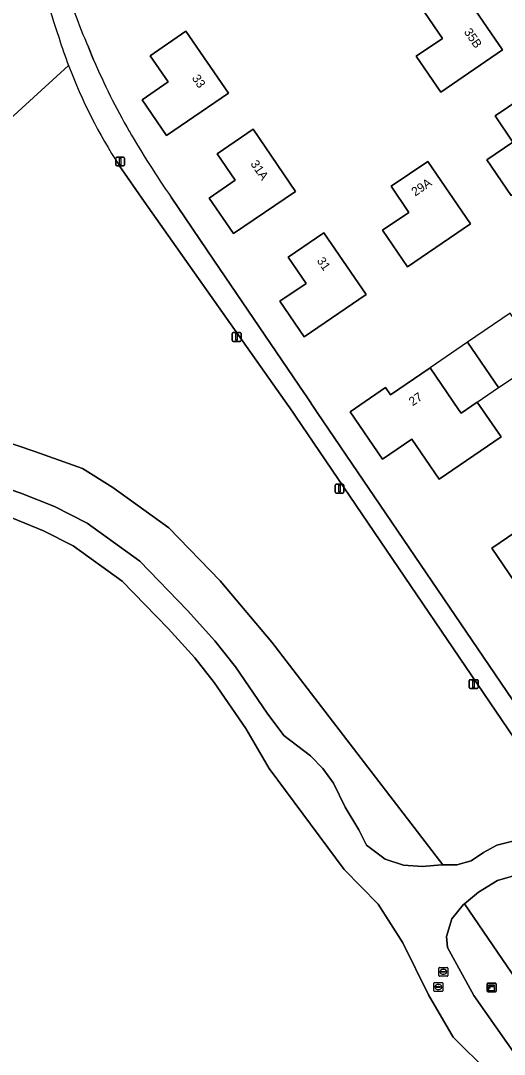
# Model space of a CAD drawing. Extents: x 155275 to 156265, y 382654 to 383635.
# Drawn here: x 155411.8 to 155466.8, y 383140.8 to 383258.3 of the extents above; entities that cross this region are included whole.
import ezdxf

# ---------------------------------------------------------------- set-up
doc = ezdxf.new("R2010")
doc.units = 0
for name, color, linetype in [('IMGEO_Erf', 7, 'Continuous'), ('IMGEO_Groenvoorziening', 7, 'Continuous'), ('IMGEO_Kast', 7, 'Continuous'), ('IMGEO_Lichtmast', 7, 'Continuous'), ('IMGEO_Pand', 7, 'Continuous'), ('IMGEO_Pand_nummerreeks', 7, 'Continuous'), ('IMGEO_Pand_overbouw', 7, 'Continuous'), ('IMGEO_Rioolput', 7, 'Continuous'), ('IMGEO_Voetpad_halfverhard', 7, 'Continuous'), ('IMGEO_Voetpad_open', 7, 'Continuous')]:
    doc.layers.add(name, color=color, linetype=linetype)

msp = doc.modelspace()

# ---------------------------------------------------------------- linework, layer by layer
at = {"layer": 'IMGEO_Erf'}
for points in [[(155428.92, 383238.24), (155433.77, 383231.09), (155444.08, 383215.94), (155444.19, 383215.77), (155445.52, 383213.79), (155474.85, 383170.58), (155512.73, 383196.49), (155448.88, 383290.13), (155420.3, 383270.55)], [(155419.52, 383255.3), (155420.11, 383253.88)], [(155468.55, 383193.62), (155465.34, 383198.36), (155476.24, 383205.79)]]:
    msp.add_lwpolyline(points, dxfattribs=at)
for points in [[(155456.77, 383254.27), (155459.75, 383256.3), (155457.7, 383259.29), (155461.75, 383262.05), (155466.57, 383255.01), (155459.55, 383250.19)], [(155428.39, 383245.27), (155425.62, 383249.31), (155428.6, 383251.38), (155426.56, 383254.33), (155430.61, 383257.14), (155435.43, 383250.08)], [(155465.72, 383247.49), (155469.81, 383250.28), (155474.6, 383243.27), (155467.56, 383238.46), (155464.78, 383242.51), (155467.74, 383244.52)], [(155436.02, 383234.12), (155433.24, 383238.16), (155436.2, 383240.2), (155434.16, 383243.2), (155438.24, 383245.97), (155443.05, 383238.92)], [(155452.95, 383234.51), (155455.92, 383236.53), (155453.92, 383239.49), (155458.08, 383242.32), (155462.91, 383235.22), (155455.79, 383230.35)], [(155444.04, 383222.38), (155441.27, 383226.44), (155444.25, 383228.45), (155442.22, 383231.43), (155446.28, 383234.21), (155451.08, 383227.18)], [(155453.28, 383216.6), (155453.84, 383215.78), (155458.35, 383218.86), (155461.58, 383214.13), (155461.87, 383213.71), (155463.7, 383214.96), (155466.4, 383211.02), (155459.35, 383206.19), (155456.25, 383210.73), (155452.94, 383208.47), (155449.27, 383213.87)]]:
    msp.add_lwpolyline(points, close=True, dxfattribs=at)
for centre, radius, start, end in [((155494.03, 383287.49), 81.16, 197.3689, 203.3673), ((155487.89, 383282.61), 73.61, 202.9709, 210.0234), ((155528.81, 383306.73), 121.11, 210.2146, 214.4373)]:
    msp.add_arc(centre, radius, start, end, dxfattribs=at)
at = {"layer": 'IMGEO_Groenvoorziening'}
for points in [[(155381.63, 383229.41), (155385.36, 383224.06), (155417.27, 383253.23)], [(155417.27, 383253.23), (155385.36, 383224.06), (155387.41, 383221.12)], [(155442.32, 383214.41), (155442.28, 383214.46), (155425.86, 383237.78), (155423.01, 383241.86)], [(155372.2, 383202.28), (155372.51, 383201.68), (155388.96, 383210.31), (155393.94, 383212.01), (155397.68, 383212.16), (155401.05, 383212.16), (155406.49, 383211.64), (155409.53, 383210.66), (155413.45, 383209.36), (155418.85, 383207.42), (155422.29, 383205.23), (155428.68, 383200.68), (155434.48, 383194.63), (155440.37, 383187.68), (155459.78, 383162.34), (155461.36, 383162.34), (155463.01, 383162.79), (155464.41, 383163.77), (155465.92, 383164.58), (155468.34, 383165.21), (155474.68, 383166.56), (155474.79, 383166.6), (155442.32, 383214.41)], [(155407.94, 383205.92), (155411.86, 383204.61), (155415.69, 383203.07), (155419.37, 383201.18), (155425.35, 383196.87), (155430.78, 383191.26), (155433.9, 383187.83), (155436.24, 383184.86), (155439.83, 383179.6), (155441.74, 383177.07), (155444.76, 383174.76), (155446.17, 383173.3), (155447.36, 383171.65), (155448.69, 383168.92), (155450.26, 383166.32), (155451.1, 383164.6), (155453.23, 383163.01), (155455.3, 383162.33), (155457.48, 383162.15), (155459.65, 383162.34), (155459.78, 383162.34), (155440.37, 383187.68), (155434.48, 383194.63), (155428.68, 383200.68), (155422.29, 383205.23), (155418.85, 383207.42), (155413.45, 383209.36), (155409.53, 383210.66)], [(155464.94, 383138.83), (155460.95, 383142.74), (155458.15, 383147.57), (155455.23, 383153.48), (155452.44, 383157.87), (155448.58, 383161.82), (155440.05, 383173.3), (155437.4, 383177.85), (155433.82, 383183.08), (155431.61, 383185.89), (155428.59, 383189.21), (155423.37, 383194.6), (155417.81, 383198.6), (155414.44, 383200.34), (155410.83, 383201.8)], [(155462.23, 383157.91), (155462.08, 383157.79), (155460.8, 383156.2), (155460.21, 383154.22), (155460.31, 383152.94), (155463.29, 383147.49), (155476.06, 383129.31), (155480.08, 383123.25), (155485.32, 383114.54), (155492.39, 383101.86), (155501.64, 383091.21), (155505.49, 383085.67), (155519.41, 383065.24), (155519.67, 383065.42), (155525.58, 383056.8)], [(155531.84, 383055.02), (155532.26, 383055.3), (155462.23, 383157.91)]]:
    msp.add_lwpolyline(points, dxfattribs=at)
msp.add_lwpolyline([(155480.03, 383158.88), (155477.83, 383162.13), (155472.81, 383162.13), (155468.62, 383161.33), (155465.99, 383160.57), (155463.85, 383159.26), (155462.23, 383157.91), (155532.26, 383055.3), (155545.15, 383064.13), (155544.46, 383065.14), (155543.8, 383064.76), (155530.65, 383083.86), (155531.33, 383084.3), (155531.27, 383084.39), (155521.54, 383098.33)], close=True, dxfattribs=at)
for centre, radius, start, end in [((155635.7, 383329.55), 231.39, 194.7339, 198.4479), ((155471.85, 383273.8), 58.33, 197.432, 200.6455), ((155472.58, 383274.03), 59.09, 200.6064, 212.9901)]:
    msp.add_arc(centre, radius, start, end, dxfattribs=at)
at = {"layer": 'IMGEO_Kast'}
for p, q in [((155464.83, 383147.98), (155464.83, 383148.82)), ((155464.83, 383148.82), (155464.83, 383147.98)), ((155464.9, 383148.91), (155465.74, 383148.91)), ((155465.74, 383148.91), (155464.9, 383148.91)), ((155465.83, 383148.83), (155465.83, 383147.99)), ((155465.83, 383147.99), (155465.83, 383148.83)), ((155465.75, 383147.91), (155464.91, 383147.91)), ((155464.91, 383147.91), (155465.75, 383147.91))]:
    msp.add_line(p, q, dxfattribs=at)
for points in [[(155465.02, 383148.7), (155465.62, 383148.7), (155465.62, 383148.61), (155465.02, 383148.61), (155465.02, 383148.7)], [(155465.02, 383148.52), (155465.62, 383148.52), (155465.62, 383148.03), (155465.02, 383148.03), (155465.02, 383148.52)]]:
    msp.add_lwpolyline(points, dxfattribs=at)
msp.add_circle((155465.11, 383148.37), 0.0377, dxfattribs=at)
for centre, start, end in [((155464.91, 383148.83), 92.4484, 184.2845), ((155464.91, 383148.83), 92.4484, 184.2845), ((155465.75, 383148.83), 2.4484, 94.2845), ((155465.75, 383148.83), 2.4484, 94.2845), ((155464.91, 383147.99), 182.4484, 274.2845), ((155464.91, 383147.99), 182.4484, 274.2845), ((155465.75, 383147.99), 272.4484, 4.2845), ((155465.75, 383147.99), 272.4484, 4.2845)]:
    msp.add_arc(centre, 0.0779, start, end, dxfattribs=at)
at = {"layer": 'IMGEO_Lichtmast'}
for p, q in [((155422.64, 383241.91), (155422.64, 383242.71)), ((155422.64, 383242.71), (155422.64, 383241.91)), ((155422.74, 383242.81), (155423.53, 383242.81)), ((155423.53, 383242.81), (155422.74, 383242.81)), ((155423.63, 383242.71), (155423.63, 383241.91)), ((155423.63, 383241.91), (155423.63, 383242.71)), ((155423.53, 383241.81), (155422.74, 383241.81)), ((155422.74, 383241.81), (155423.53, 383241.81)), ((155435.87, 383221.96), (155435.87, 383222.76)), ((155435.87, 383222.76), (155435.87, 383221.96)), ((155435.97, 383222.86), (155436.76, 383222.86)), ((155436.76, 383222.86), (155435.97, 383222.86)), ((155436.86, 383222.76), (155436.86, 383221.96)), ((155436.86, 383221.96), (155436.86, 383222.76)), ((155436.76, 383221.86), (155435.97, 383221.86)), ((155435.97, 383221.86), (155436.76, 383221.86)), ((155447.55, 383204.72), (155447.55, 383205.52)), ((155447.55, 383205.52), (155447.55, 383204.72)), ((155447.65, 383205.62), (155448.44, 383205.62)), ((155448.44, 383205.62), (155447.65, 383205.62)), ((155448.44, 383204.62), (155447.65, 383204.62)), ((155447.65, 383204.62), (155448.44, 383204.62)), ((155448.54, 383205.52), (155448.54, 383204.72)), ((155448.54, 383204.72), (155448.54, 383205.52)), ((155462.79, 383182.5), (155462.79, 383183.3)), ((155462.79, 383183.3), (155462.79, 383182.5)), ((155462.89, 383183.4), (155463.68, 383183.4)), ((155463.68, 383183.4), (155462.89, 383183.4)), ((155463.68, 383182.4), (155462.89, 383182.4)), ((155462.89, 383182.4), (155463.68, 383182.4)), ((155463.78, 383183.3), (155463.78, 383182.5)), ((155463.78, 383182.5), (155463.78, 383183.3))]:
    msp.add_line(p, q, dxfattribs=at)
for points in [[(155423.06, 383242.69), (155423.21, 383242.69), (155423.21, 383241.94), (155423.06, 383241.94), (155423.06, 383242.69)], [(155436.29, 383222.74), (155436.44, 383222.74), (155436.44, 383221.99), (155436.29, 383221.99), (155436.29, 383222.74)], [(155447.97, 383205.5), (155448.12, 383205.5), (155448.12, 383204.75), (155447.97, 383204.75), (155447.97, 383205.5)], [(155463.21, 383183.27), (155463.36, 383183.27), (155463.36, 383182.52), (155463.21, 383182.52), (155463.21, 383183.27)]]:
    msp.add_lwpolyline(points, dxfattribs=at)
for centre, start, end in [((155422.74, 383242.71), 90, 180), ((155422.74, 383242.71), 90, 180), ((155423.53, 383242.71), 0, 90), ((155423.53, 383242.71), 360, 90), ((155422.74, 383241.91), 180, 270), ((155422.74, 383241.91), 180, 270), ((155423.53, 383241.91), 270, 0), ((155423.53, 383241.91), 270, 0), ((155435.97, 383222.76), 90, 180), ((155435.97, 383222.76), 90, 180), ((155436.76, 383222.76), 0, 90), ((155436.76, 383222.76), 360, 90), ((155435.97, 383221.96), 180, 270), ((155435.97, 383221.96), 180, 270), ((155436.76, 383221.96), 270, 0), ((155436.76, 383221.96), 270, 0), ((155447.65, 383205.52), 90, 180), ((155447.65, 383205.52), 90, 180), ((155447.65, 383204.72), 180, 270), ((155447.65, 383204.72), 180, 270), ((155448.44, 383205.52), 0, 90), ((155448.44, 383205.52), 360, 90), ((155448.44, 383204.72), 270, 0), ((155448.44, 383204.72), 270, 0), ((155462.89, 383183.3), 90, 180), ((155462.89, 383183.3), 90, 180), ((155462.89, 383182.5), 180, 270), ((155462.89, 383182.5), 180, 270), ((155463.68, 383183.3), 0, 90), ((155463.68, 383183.3), 360, 90), ((155463.68, 383182.5), 270, 0), ((155463.68, 383182.5), 270, 0)]:
    msp.add_arc(centre, 0.1, start, end, dxfattribs=at)
at = {"layer": 'IMGEO_Pand'}
for points in [[(155461.75, 383262.05), (155457.7, 383259.29), (155459.75, 383256.3), (155456.77, 383254.27), (155459.55, 383250.19), (155466.57, 383255.01)], [(155430.61, 383257.14), (155426.56, 383254.33), (155428.6, 383251.38), (155425.62, 383249.31), (155428.39, 383245.27), (155435.43, 383250.08)], [(155469.81, 383250.28), (155465.72, 383247.49), (155467.74, 383244.52), (155464.78, 383242.51), (155467.56, 383238.46), (155474.6, 383243.27)], [(155438.24, 383245.97), (155434.16, 383243.2), (155436.2, 383240.2), (155433.24, 383238.16), (155436.02, 383234.12), (155443.05, 383238.92)], [(155458.08, 383242.32), (155453.92, 383239.49), (155455.92, 383236.53), (155452.95, 383234.51), (155455.79, 383230.35), (155462.91, 383235.22)], [(155446.28, 383234.21), (155442.22, 383231.43), (155444.25, 383228.45), (155441.27, 383226.44), (155444.04, 383222.38), (155451.08, 383227.18)], [(155463.7, 383214.96), (155461.87, 383213.71), (155461.58, 383214.13), (155458.35, 383218.86), (155453.84, 383215.78), (155453.28, 383216.6), (155449.27, 383213.87), (155452.94, 383208.47), (155456.25, 383210.73), (155459.35, 383206.19), (155466.4, 383211.02)], [(155480.83, 383202.03), (155482.22, 383202.97), (155476.21, 383211.82), (155473.43, 383209.92), (155476.24, 383205.79), (155465.34, 383198.36), (155468.55, 383193.62), (155471.85, 383195.86)]]:
    msp.add_lwpolyline(points, close=True, dxfattribs=at)
at = {"layer": 'IMGEO_Pand_overbouw'}
for points in [[(155462.6, 383221.76), (155466.12, 383216.61), (155466.97, 383217.18), (155470.96, 383219.9), (155470.82, 383220.1), (155470.67, 383220.31), (155467.43, 383225.06)], [(155462.6, 383221.76), (155458.35, 383218.86), (155461.58, 383214.13), (155461.87, 383213.71), (155463.7, 383214.96), (155466.12, 383216.61)]]:
    msp.add_lwpolyline(points, close=True, dxfattribs=at)
at = {"layer": 'IMGEO_Rioolput'}
for p, q in [((155459.34, 383149.76), (155459.34, 383150.61)), ((155459.42, 383150.69), (155460.27, 383150.69)), ((155460.34, 383150.61), (155460.34, 383149.76)), ((155460.27, 383149.69), (155459.42, 383149.69)), ((155459.6, 383150.18), (155459.6, 383150.19)), ((155460.04, 383150.14), (155459.64, 383150.14)), ((155459.65, 383150.23), (155460.04, 383150.23)), ((155459.83, 383150.47), (155459.86, 383150.47)), ((155459.85, 383149.91), (155459.83, 383149.91)), ((155460.09, 383150.19), (155460.09, 383150.18)), ((155458.76, 383148.04), (155458.76, 383148.89)), ((155458.84, 383148.96), (155459.69, 383148.96)), ((155459.02, 383148.46), (155459.02, 383148.47)), ((155459.46, 383148.42), (155459.06, 383148.42)), ((155459.07, 383148.51), (155459.46, 383148.51)), ((155459.25, 383148.74), (155459.28, 383148.74)), ((155459.27, 383148.18), (155459.25, 383148.18)), ((155459.51, 383148.47), (155459.51, 383148.46)), ((155459.77, 383148.89), (155459.77, 383148.04)), ((155459.69, 383147.96), (155458.84, 383147.96))]:
    msp.add_line(p, q, dxfattribs=at)
for points in [[(155459.34, 383149.76), (155459.34, 383150.61)], [(155459.42, 383150.69), (155460.27, 383150.69)], [(155460.34, 383150.61), (155460.34, 383149.76)], [(155460.27, 383149.69), (155459.42, 383149.69)], [(155458.76, 383148.04), (155458.76, 383148.89)], [(155458.84, 383148.96), (155459.69, 383148.96)], [(155459.77, 383148.89), (155459.77, 383148.04)], [(155459.69, 383147.96), (155458.84, 383147.96)]]:
    msp.add_lwpolyline(points, dxfattribs=at)
for centre, radius, start, end in [((155459.42, 383150.61), 0.0765, 91.552, 178.448), ((155459.42, 383150.61), 0.0765, 91.552, 178.448), ((155460.27, 383150.61), 0.0765, 1.552, 88.448), ((155460.27, 383150.61), 0.0765, 1.552, 88.448), ((155459.42, 383149.76), 0.0765, 181.552, 268.448), ((155459.42, 383149.76), 0.0765, 181.552, 268.448), ((155459.64, 383150.19), 0.0403, 85.8775, 175.7526), ((155459.64, 383150.18), 0.0366, 178.938, 274.7102), ((155460.05, 383150.19), 0.0386, 1.7309, 96.639), ((155460.04, 383150.19), 0.043, 264.8664, 352.4533), ((155460.27, 383149.76), 0.0765, 271.552, 358.448), ((155460.27, 383149.76), 0.0765, 271.552, 358.448), ((155458.84, 383148.89), 0.0765, 91.552, 178.448), ((155458.84, 383148.89), 0.0765, 91.552, 178.448), ((155459.06, 383148.47), 0.0403, 85.8775, 175.7526), ((155459.06, 383148.46), 0.0366, 178.938, 274.7102), ((155459.47, 383148.47), 0.0386, 1.7309, 96.639), ((155459.46, 383148.46), 0.043, 264.8664, 352.4533), ((155459.69, 383148.89), 0.0765, 1.552, 88.448), ((155459.69, 383148.89), 0.0765, 1.552, 88.448), ((155458.84, 383148.04), 0.0765, 181.552, 268.448), ((155458.84, 383148.04), 0.0765, 181.552, 268.448), ((155459.69, 383148.04), 0.0765, 271.552, 358.448), ((155459.69, 383148.04), 0.0765, 271.552, 358.448)]:
    msp.add_arc(centre, radius, start, end, dxfattribs=at)
for centre, major_axis, ratio, start_param, end_param in [((155459.83, 383150.19), (-0.387, 0.002), 0.722429, 4.712389, 7.853982), ((155459.85, 383150.19), (-0.39, 0.002), 0.717154, 1.570796, 4.712389), ((155459.25, 383148.46), (-0.387, 0.002), 0.722429, 4.712389, 7.853982), ((155459.28, 383148.46), (-0.39, 0.002), 0.717154, 1.570796, 4.712389)]:
    msp.add_ellipse(centre, major_axis=major_axis, ratio=ratio, start_param=start_param, end_param=end_param, dxfattribs=at)
at = {"layer": 'IMGEO_Voetpad_halfverhard'}
for points in [[(155468.34, 383165.21), (155465.92, 383164.58), (155464.41, 383163.77), (155463.01, 383162.79), (155461.36, 383162.34), (155459.78, 383162.34), (155459.65, 383162.34), (155457.48, 383162.15), (155455.3, 383162.33), (155453.23, 383163.01), (155451.1, 383164.6), (155450.26, 383166.32), (155448.69, 383168.92), (155447.36, 383171.65), (155446.17, 383173.3), (155444.76, 383174.76), (155441.74, 383177.07), (155439.83, 383179.6), (155436.24, 383184.86), (155433.9, 383187.83), (155430.78, 383191.26), (155425.35, 383196.87), (155419.37, 383201.18), (155415.69, 383203.07), (155411.86, 383204.61), (155407.94, 383205.92)], [(155410.83, 383201.8), (155414.44, 383200.34), (155417.81, 383198.6), (155423.37, 383194.6), (155428.59, 383189.21), (155431.61, 383185.89), (155433.82, 383183.08), (155437.4, 383177.85), (155440.05, 383173.3), (155448.58, 383161.82), (155452.44, 383157.87), (155455.23, 383153.48), (155458.15, 383147.57), (155460.95, 383142.74), (155464.94, 383138.83)], [(155460.31, 383152.94), (155460.21, 383154.22), (155460.8, 383156.2), (155462.08, 383157.79), (155462.23, 383157.91), (155463.85, 383159.26), (155465.99, 383160.57), (155468.62, 383161.33)], [(155476.06, 383129.31), (155463.29, 383147.49), (155460.31, 383152.94)]]:
    msp.add_lwpolyline(points, dxfattribs=at)
at = {"layer": 'IMGEO_Voetpad_open'}
for points in [[(155420.11, 383253.88), (155419.52, 383255.3)], [(155423.01, 383241.86), (155425.86, 383237.78), (155442.28, 383214.46), (155442.32, 383214.41), (155474.79, 383166.6), (155476.98, 383167.45), (155474.85, 383170.58), (155445.52, 383213.79), (155444.19, 383215.77), (155444.08, 383215.94), (155433.77, 383231.09), (155428.92, 383238.24)]]:
    msp.add_lwpolyline(points, dxfattribs=at)
for centre, radius, start, end in [((155635.7, 383329.55), 231.39, 194.7339, 198.4479), ((155494.03, 383287.49), 81.16, 197.3689, 203.3673), ((155471.85, 383273.8), 58.33, 197.432, 200.6455), ((155472.58, 383274.03), 59.09, 200.6064, 212.9901), ((155487.89, 383282.61), 73.61, 202.9709, 210.0234), ((155528.81, 383306.73), 121.11, 210.2146, 214.4373)]:
    msp.add_arc(centre, radius, start, end, dxfattribs=at)

# ---------------------------------------------------------------- texts
at = {"layer": 'IMGEO_Pand_nummerreeks'}
for s, rotation, p in [('35B', 304.3257, (155462.14, 383257.05)), ('33', 304.3372, (155431.24, 383251.79)), ('31A', 304.3028, (155437.89, 383242.05)), ('29A', 34.2113, (155456.65, 383238.32)), ('31', 304.2856, (155445.43, 383231.03)), ('27', 34.3431, (155456.35, 383214.47))]:
    msp.add_text(s, height=1, rotation=rotation, dxfattribs=at).set_placement(p)

doc.saveas('drawing.dxf')
